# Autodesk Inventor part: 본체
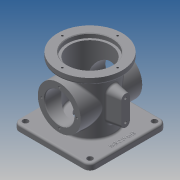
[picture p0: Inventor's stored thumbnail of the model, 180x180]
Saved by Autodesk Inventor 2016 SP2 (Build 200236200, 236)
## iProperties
Created: 2017-08
Part Number: 본체
Material: 알루미늄 6061
Document SubType Name: Modeling
Designer: mduedu
Density: 2.71 g/cm^3
Mass: 951.115 g
Surface Area: 966.539 cm^2
Volume: 350.965 cm^3
Appearance: 기본값
Author: mduedu
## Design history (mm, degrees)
sketch "스케치1"
  geometry: L1 (-62.5, -62.5)-(62.5, -62.5); L2 (62.5, -62.5)-(62.5, 62.5); L3 (62.5, 62.5)-(-62.5, 62.5); L4 (-62.5, 62.5)-(-62.5, -62.5); L5 (-62.5, -62.5)-(62.5, 62.5); L6 (62.5, -62.5)-(-62.5, 62.5); 1 further point
  constraints: 12 end point, 2 midpoint, 2 parallel, 1 horizontal, 1 perpendicular
  dimensions: "d232" = 125 distance of L3.end L2.end; "d233" = 125 distance of L2.end L1.end
extrude "돌출1" new body sketch "스케치1" distance "d5" = 10; taper "d6" = 0 deg
sketch "스케치2"
  geometry: C1 r 38 at (0, 0); 1 further point
  constraints: 1 centre point, 1 coincident
  dimensions: "d111" = 76 diameter of C1
extrude "돌출2" join sketch "스케치2" distance "d12" = 88; taper "d13" = 0 deg
sketch "스케치3"
  geometry: C1 r 52.5 at (0, 0); 1 further point
  constraints: 1 centre point, 1 coincident
  dimensions: "d114" = 105 diameter of C1
extrude "돌출3" join sketch "스케치3" distance "d19" = 10; taper "d20" = 0 deg
sketch "스케치4"
  geometry: C1 r 33 at (0, 0); 1 further point
  constraints: 1 centre point, 1 coincident
  dimensions: "d115" = 66 diameter of C1
extrude "돌출4" cut sketch "스케치4" distance "d26" = 86; taper "d27" = 0 deg
sketch "스케치5"
  geometry: C1 r 37 at (0, 0); 1 further point
  constraints: 1 centre point, 1 coincident
  dimensions: "d116" = 74 diameter of C1
extrude "돌출5" cut sketch "스케치5" distance "d29" = 7; taper "d30" = 0 deg
node "작업 평면1"
sketch "스케치18"
  geometry: L1 (-62.5, 0)-(62.5, 0) reference; C1 r 35 at (0, 54); 1 further point
  constraints: 1 centre point, 1 vertical alignment
  dimensions: "d118" = 70 diameter of C1; "d234" = 54 distance from line of C1.centre L1
extrude "돌출9" join sketch "스케치18" stored distance "d120" = 10; taper "d121" = 0 deg
hole "구멍8" diameter "d124" = 48; stored, may be unused: countersink angle "d128" = 90 deg, drill point angle "d130" = 118 deg; dims "d122" = 10, "d123" = 10, "d125" = 6, "d126" = 4, "d127" = 2, "d129" = 8
sketch "스케치9"
  geometry: C1 r 33 at (0, 0); 1 further point
  constraints: 1 centre point, 1 coincident
  dimensions: "d131" = 66 diameter of C1
extrude "돌출8" cut sketch "스케치9" distance "d43" = 16; taper "d44" = 0 deg
node "작업 평면2"
fillet "모깎기9" dims "d137" = 3
fillet "모깎기10" dims "d138" = 3
chamfer "모따기2" distance "d139" = 1; stored, may be unused: second distance "d140" = 2, angle "d141" = 45 deg
fillet "모깎기11" dims "d142" = 3
fillet "모깎기12" dims "d143" = 3
fillet "모깎기13" dims "d144" = 3
node "작업 평면3"
sketch "스케치20"
  geometry: L1 (108, -52.5)-(108, 52.5) reference; L2 (37, 7)-(71, 7); L3 (37, -7)-(71, -7); L4 (0, -33)-(0, 33) reference; A1 r 7 centre (37, 0) between (37, 7) and (37, -7); A2 r 7 centre (71, 0) between (71, 7) and (71, -7); 1 further point
  constraints: 4 end point, 4 point on circle, 3 tangent, 2 centre point, 2 horizontal alignment, 1 parallel, 1 perpendicular
  dimensions: "d203" = 14 diameter of A1; "d206" = 30 distance edge to line of A2 L1; "d207" = 48 dimension on A2 A1 (derived); "d236" = 30 distance edge to line of A1 L4
extrude "돌출10" join sketch "스케치20" stored distance "d152" = 10; taper "d153" = 10 deg
sketch "스케치21"
  geometry: C1 r 7 at (0, 71) reference; C2 r 7 at (0, 37) reference; 3 further points
  constraints: 2 coincident
hole "구멍12" sketch "스케치21" at (0, 71), (0, 37) diameter "d219" = 4.134; stored, may be unused: countersink angle "d223" = 90 deg, drill point angle "d225" = 118 deg; dims "d220" = 6, "d221" = 4, "d222" = 2, "d224" = 8
fillet "모깎기18" dims "d229" = 3
sketch "스케치23"
  geometry: C1 r 20 at (0, 0); 1 further point
  constraints: 1 centre point, 1 coincident
  dimensions: "d168" = 40 diameter of C1
extrude "돌출12" cut sketch "스케치23" stored distance "d169" = 148.25; taper "d170" = 0 deg
sketch "스케치28"
  geometry: L1 (62.5, -62.5)-(62.5, 62.5) reference; 2 further points
  constraints: 1 horizontal alignment, 1 other
  dimensions: "d238" = 10 distance from line of point (52.5, 0) L1
feature "엠보싱4" sketch "스케치28" dims "d239" = 0.5, "d240" = 0
sketch "스케치25" dims "d178" = 58
  geometry: C1 r 35 at (0, 0) reference; 3 further points
  constraints: 2 vertical alignment, 1 coincident, 2 other
hole "구멍10" sketch "스케치25" at (0, 29) diameter "d179" = 3.242; stored, may be unused: countersink angle "d183" = 90 deg, drill point angle "d185" = 118 deg; dims "d180" = 4, "d181" = 4, "d182" = 2, "d184" = 6
sketch "스케치26" dims "d189" = 90
  geometry: 3 further points
  constraints: 2 vertical alignment, 1 coincident, 2 other
hole "구멍11" sketch "스케치26" at (0, 45) diameter "d190" = 3.242; stored, may be unused: countersink angle "d194" = 90 deg, drill point angle "d196" = 118 deg; dims "d191" = 4, "d192" = 4, "d193" = 2, "d195" = 6
chamfer "모따기4" distance "d200" = 1; stored, may be unused: second distance "d201" = 2, angle "d202" = 45 deg
fillet "모깎기19" dims "d241" = 10
sketch "스케치29"
  geometry: A1 r 10 centre (-52.5, 52.5) between (-52.5, 62.5) and (-62.5, 52.5) reference; A2 r 10 centre (52.5, 52.5) between (62.5, 52.5) and (52.5, 62.5) reference; A3 r 10 centre (52.5, -52.5) between (52.5, -62.5) and (62.5, -52.5) reference; A4 r 10 centre (-52.5, -52.5) between (-62.5, -52.5) and (-52.5, -62.5) reference; 5 further points
  constraints: 4 coincident
hole "구멍13" sketch "스케치29" at (-52.5, 52.5), (52.5, 52.5), (52.5, -52.5), (-52.5, -52.5) diameter "d242" = 9; stored, may be unused: countersink angle "d246" = 90 deg, drill point angle "d248" = 118 deg; dims "d243" = 6, "d244" = 4, "d245" = 2, "d247" = 8
fillet "모깎기20" dims "d249" = 3
node "솔리드1"
mirror "대칭2"
pattern_circular "원형 패턴1" dims angle "d187" = 360 deg
mirror "대칭3"
pattern_circular "원형 패턴2" dims angle "d198" = 360 deg
other parameters: "d147" = 58
